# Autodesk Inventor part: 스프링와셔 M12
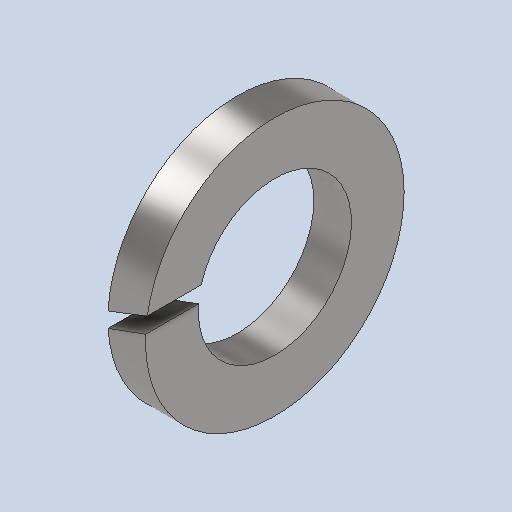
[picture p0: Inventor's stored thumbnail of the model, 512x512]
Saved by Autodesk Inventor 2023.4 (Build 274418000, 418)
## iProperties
Created: 2024-04
Part Number: 스프링와셔 M12
Material: 강철, 연강
Description: 스프링 잠금 와셔
Document SubType Name: Modeling
Designer: Edu03
Density: 7.85 g/cm^3
Appearance: 기본값
Author: jhkim
Sending System: Autodesk Inventor 2025
Preprocessor: ST-DEVELOPER v20
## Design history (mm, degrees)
feature "Solid1"
node "솔리드1"
